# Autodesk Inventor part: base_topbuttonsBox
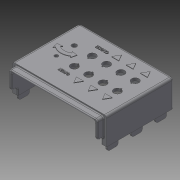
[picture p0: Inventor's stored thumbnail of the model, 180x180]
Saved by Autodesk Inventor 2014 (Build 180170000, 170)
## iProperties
Created: 2014-04
Part Number: base_topbuttonsBox
Material: Generic
Document SubType Name: Modeling
Designer: t_emanb
Density: 1 g/cm^3
Appearance: Default
Author: t_emanb
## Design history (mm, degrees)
sketch "Sketch1"
  geometry: L1 (0, 0)-(133.35, 0); L2 (133.35, 0)-(133.35, 95.25); L3 (133.35, 95.25)-(0, 95.25); L4 (0, 95.25)-(0, 0)
  constraints: 8 end point, 2 parallel, 1 horizontal, 1 perpendicular
  dimensions: "d0" = 133.35 distance of L1.start L1.end; "d1" = 95.25 distance of L3.end L1.start
extrude "Extrusion1" new body sketch "Sketch1" distance "d2" = 5.08; taper "d3" = 0 deg
sketch "Sketch2"
  geometry: L1 (0, 0)-(-133.35, 0) reference; L2 (0, 95.25)-(0, 0) reference; L3 (-133.35, 95.25)-(0, 95.25) reference; L4 (-133.35, 0)-(-133.35, 95.25) reference; L5 (-7.62, 95.25)-(-7.62, 7.62); L6 (-7.62, 7.62)-(-125.73, 7.62); L7 (-125.73, 7.62)-(-125.73, 95.25)
  constraints: 6 end point, 2 point on line
  dimensions: "d4" = 7.62 distance between parallel lines of L1 L6; "d5" = 7.62 distance between parallel lines of L2 L5 (= d4); "d6" = 7.62 distance between parallel lines of L4 L7 (= d4)
extrude "Extrusion2" join sketch "Sketch2" distance "d7" = 33.02; taper "d8" = 0 deg
sketch "Sketch3" dims "d24" = 25.4, "d104" = 25.4
  geometry: L1 (0, 0)-(-133.35, 0) reference; L2 (-133.35, 0)-(-133.35, -95.25) reference; L3 (-133.35, -95.25)-(0, -95.25) reference; L4 (-62.65, -37.9)-(-62.65, -36.829); L5 (-64.35, -36.829)-(-64.35, -37.9); L6 (-64.35, -37.9)-(-62.65, -37.9); L7 (-64.35, -51)-(-62.65, -51); L8 (-64.35, -52.071)-(-64.35, -51); L9 (-62.65, -51)-(-62.65, -52.071); L10 (-42.33, -37.9)-(-42.33, -36.829); L11 (-43.18, -26.6)-(-43.18, -33.684); L12 (-17.78, -19.05)-(-17.78, -69.85); L13 (-43.18, -19.05)-(-43.18, -69.85); L14 (-66.675, -6.762)-(-66.675, -84.867); L15 (-115.57, -19.05)-(-17.78, -19.05); L16 (-17.78, -69.85)-(-115.57, -69.85); L17 (-115.57, -44.45)-(-17.78, -44.45); L18 (-115.57, -69.85)-(-115.57, -19.05); L19 (-84.67, -36.829)-(-84.67, -37.9); L20 (-84.67, -37.9)-(-82.97, -37.9); L21 (-82.97, -37.9)-(-82.97, -36.829); L22 (-44.03, -52.071)-(-44.03, -51); L23 (-42.33, -51)-(-42.33, -52.071); L24 (-44.03, -51)-(-42.33, -51); L25 (-44.03, -36.829)-(-44.03, -37.9); L26 (-44.03, -37.9)-(-42.33, -37.9); L27 (-84.67, -52.071)-(-84.67, -51); L28 (-84.67, -51)-(-82.97, -51); L29 (-82.97, -51)-(-82.97, -52.071); L30 (-66.675, -95.25)-(-66.675, 0); L31 (-23.71, -37.9)-(-22.01, -37.9); L32 (-22.01, -37.9)-(-22.01, -36.829); L33 (-23.71, -36.829)-(-23.71, -37.9); L34 (-23.71, -51)-(-22.01, -51); L35 (-22.01, -51)-(-22.01, -52.071); L36 (-23.71, -52.071)-(-23.71, -51); C1 r 3.4 at (-109.22, -31.75); C2 r 2.54 at (-109.22, -57.15); A1 r 5.15 centre (-63.5, -31.75) between (-62.65, -36.829) and (-64.35, -36.829); A2 r 5.15 centre (-63.5, -57.15) between (-64.35, -52.071) and (-62.65, -52.071); A3 r 5.15 centre (-83.82, -31.75) between (-82.97, -36.829) and (-84.67, -36.829); A4 r 5.15 centre (-43.18, -57.15) between (-44.03, -52.071) and (-42.33, -52.071); A5 r 5.15 centre (-43.18, -31.75) between (-42.33, -36.829) and (-44.03, -36.829); A6 r 5.15 centre (-83.82, -57.15) between (-84.67, -52.071) and (-82.97, -52.071); A7 r 5.15 centre (-22.86, -31.75) between (-22.01, -36.829) and (-23.71, -36.829); A8 r 5.15 centre (-22.86, -57.15) between (-23.71, -52.071) and (-22.01, -52.071); 3 further points
  constraints: 66 end point, 20 point on circle, 10 centre point, 6 symmetric about line, 4 midpoint, 4 parallel, 4 perpendicular, 4 point on line, 3 horizontal, 1 collinear, 1 vertical alignment, 60 other
  dimensions: "d13" = 50.8 distance of L12.start L12.end; "d14" = 10.3 diameter of A5; "d15" = 1.7 distance of L25.end L10.start; "d16" = 11.3 distance from line of L11.start L26; "d18" = 25.4 distance of A4.centre A5.centre; "d19" = 20.32 distance of L25.end L5.end; "d20" = 5.08 diameter of C2; "d21" = 6.8 diameter of C1; "d22" = 25.4 distance of C2.centre C1.centre; "d23" = 6.35 distance from line of L18 C2.centre; "d25" = 17.78 distance between parallel lines of L2 L18; "d26" = 44.45 distance between parallel lines of L1 L17; "d97" = 25.4 distance of C1.centre A3.centre; "d101" = 20.32 distance of L25.end L31.start
extrude "Extrusion3" cut sketch "Sketch3" stored distance "d27" = 33.02; taper "d28" = 0 deg
sketch "Sketch4" dims "d37" = 25.4, "d48" = 25.4
  geometry: L1 (-133.35, 0)-(0, 0) reference; L2 (-7.62, 7.62)-(-125.73, 7.62) reference; L3 (-125.73, 7.62)-(-125.73, 95.25) reference; L4 (-133.35, 95.25)-(-133.35, 0) reference; L5 (-125.73, 4.953)-(-110.49, 4.953); L6 (-110.49, 4.953)-(-110.49, 2.667); L7 (-110.49, 2.667)-(-125.73, 2.667); L8 (-125.73, 2.667)-(-125.73, 4.953); L9 (-76.2, 2.667)-(-91.44, 2.667); L10 (-76.2, 4.953)-(-76.2, 2.667); L11 (-91.44, 4.953)-(-76.2, 4.953); L12 (-91.44, 2.667)-(-91.44, 4.953); L13 (-41.91, 2.667)-(-57.15, 2.667); L14 (-41.91, 4.953)-(-41.91, 2.667); L15 (-57.15, 4.953)-(-41.91, 4.953); L16 (-57.15, 2.667)-(-57.15, 4.953); L17 (-7.62, 2.667)-(-22.86, 2.667); L18 (-7.62, 4.953)-(-7.62, 2.667); L19 (-22.86, 4.953)-(-7.62, 4.953); L20 (-22.86, 2.667)-(-22.86, 4.953); L21 (-130.683, 7.62)-(-128.397, 7.62); L22 (-128.397, 7.62)-(-128.397, 22.86); L23 (-128.397, 22.86)-(-130.683, 22.86); L24 (-130.683, 22.86)-(-130.683, 7.62); L25 (-130.683, 57.15)-(-130.683, 41.91); L26 (-130.683, 41.91)-(-128.397, 41.91); L27 (-128.397, 41.91)-(-128.397, 57.15); L28 (-128.397, 57.15)-(-130.683, 57.15); L29 (-130.683, 91.44)-(-130.683, 76.2); L30 (-130.683, 76.2)-(-128.397, 76.2); L31 (-128.397, 76.2)-(-128.397, 91.44); L32 (-128.397, 91.44)-(-130.683, 91.44); L33 (-66.675, 0)-(-66.675, 95.25); L34 (-4.953, 22.86)-(-2.667, 22.86); L35 (-4.953, 7.62)-(-4.953, 22.86); L36 (-2.667, 22.86)-(-2.667, 7.62); L37 (-2.667, 7.62)-(-4.953, 7.62); L38 (-2.667, 41.91)-(-4.953, 41.91); L39 (-4.953, 41.91)-(-4.953, 57.15); L40 (-4.953, 57.15)-(-2.667, 57.15); L41 (-2.667, 57.15)-(-2.667, 41.91); L42 (-2.667, 76.2)-(-4.953, 76.2); L43 (-2.667, 91.44)-(-2.667, 76.2); L44 (-4.953, 91.44)-(-2.667, 91.44); L45 (-4.953, 76.2)-(-4.953, 91.44)
  constraints: 82 end point, 12 symmetric about line, 4 parallel, 3 horizontal, 3 perpendicular, 2 collinear, 1 midpoint, 1 vertical, 40 other
  dimensions: "d29" = 2.286 distance of L7.end L5.start; "d30" = 2.667 distance between parallel lines of L1 L7; "d31" = 15.24 distance of L6.end L7.end; "d34" = 34.29 distance of L6.end L9.start; "d40" = 2.286 distance of L21.start L21.end (= d29); "d41" = 15.24 distance of L23.end L21.start (= d31); "d42" = 2.667 distance between parallel lines of L4 L24 (= d30); "d45" = 34.29 distance of L23.end L25.start
extrude "Extrusion4" join sketch "Sketch4" distance "d50" = 8.89; taper "d51" = 0 deg
sketch "Sketch6"
  geometry: L1 (7.62, -5.08)-(125.73, -5.08) reference; L2 (125.73, -5.08)-(125.73, -38.1) reference; L3 (133.35, -38.1)-(133.35, 0) reference; L4 (7.62, -5.08)-(7.62, -38.1) reference; L5 (7.62, -27.94)-(3.81, -27.94); L6 (3.81, -27.94)-(3.81, -2.54); L7 (3.81, -2.54)-(129.54, -2.54); L8 (129.54, -2.54)-(129.54, -27.94); L9 (129.54, -27.94)-(125.73, -27.94); 1 further point
  constraints: 10 end point, 3 perpendicular, 2 parallel, 2 point on line, 1 collinear
  dimensions: "d55" = 2.54 distance between parallel lines of L7 L1; "d56" = 3.81 distance between parallel lines of L8 L2; "d57" = 3.81 distance between parallel lines of L4 L6; "d58" = 25.4 distance of L5.end L6.end
extrude "Extrusion6" join sketch "Sketch6" distance "d59" = 8.89; taper "d60" = 0 deg
sketch "Sketch7"
  geometry: L1 (-42.33, 52.071)-(-42.33, 51) reference; L2 (-42.33, 51)-(-44.03, 51) reference; L3 (-44.03, 51)-(-44.03, 52.071) reference; L4 (-44.03, 36.829)-(-44.03, 37.9) reference; L5 (-44.03, 37.9)-(-42.33, 37.9) reference; L6 (-42.33, 37.9)-(-42.33, 36.829) reference; L7 (-64.35, 36.829)-(-64.35, 37.9) reference; L8 (-64.35, 37.9)-(-62.65, 37.9) reference; L9 (-62.65, 37.9)-(-62.65, 36.829) reference; L10 (-64.35, 51)-(-64.35, 52.071) reference; L11 (-62.65, 52.071)-(-62.65, 51) reference; L12 (-62.65, 51)-(-64.35, 51) reference; L13 (-84.67, 36.829)-(-84.67, 37.9) reference; L14 (-84.67, 37.9)-(-82.97, 37.9) reference; L15 (-82.97, 37.9)-(-82.97, 36.829) reference; L16 (-82.97, 52.071)-(-82.97, 51) reference; L17 (-82.97, 51)-(-84.67, 51) reference; L18 (-84.67, 51)-(-84.67, 52.071) reference; L19 (-116.205, 67.31)-(-15.875, 67.31); L20 (-12.7, 64.135)-(-12.7, 24.765); L21 (-15.875, 21.59)-(-116.205, 21.59); L22 (-119.38, 24.765)-(-119.38, 64.135); C1 r 2.54 at (-109.22, 57.15) reference; C2 r 3.4 at (-109.22, 31.75) reference; A1 r 5.15 centre (-43.18, 57.15) between (-42.33, 52.071) and (-44.03, 52.071) reference; A2 r 5.15 centre (-43.18, 31.75) between (-44.03, 36.829) and (-42.33, 36.829) reference; A3 r 5.15 centre (-63.5, 31.75) between (-64.35, 36.829) and (-62.65, 36.829) reference; A4 r 5.15 centre (-63.5, 57.15) between (-62.65, 52.071) and (-64.35, 52.071) reference; A5 r 5.15 centre (-83.82, 31.75) between (-84.67, 36.829) and (-82.97, 36.829) reference; A6 r 5.15 centre (-83.82, 57.15) between (-82.97, 52.071) and (-84.67, 52.071) reference; A7 r 3.175 centre (-116.205, 64.135) between (-116.205, 67.31) and (-119.38, 64.135); A8 r 3.175 centre (-116.205, 24.765) between (-119.38, 24.765) and (-116.205, 21.59); A9 r 3.175 centre (-15.875, 24.765) between (-15.875, 21.59) and (-12.7, 24.765); A10 r 3.175 centre (-15.875, 64.135) between (-12.7, 64.135) and (-15.875, 67.31); A11 r 5.15 centre (-22.86, 57.15) between (-22.01, 52.071) and (-23.71, 52.071) reference; 1 further point
  constraints: 8 end point, 8 point on circle, 8 tangent, 4 centre point, 3 equal radius, 2 parallel, 1 horizontal, 1 perpendicular
  dimensions: "d61" = 10.16 distance from line of A3.centre L21; "d62" = 10.16 distance from line of A4.centre L19; "d64" = 10.16 distance from line of L22 C2.centre; "d65" = 3.175 radius of A7; "d113" = 10.16 distance from line of L20 A11.centre
extrude "Extrusion7" cut sketch "Sketch7" distance "d66" = 1.27; taper "d67" = 0 deg
sketch "Sketch8" dims "d75" = 25.4, "d111" = 25.4
  geometry: L1 (-133.35, 0)-(-133.35, -95.25) reference; L2 (-83.82, -10.644)-(-78.74, -19.443); L3 (-78.74, -19.443)-(-88.9, -19.443); L4 (-88.9, -19.443)-(-83.82, -10.644); L5 (-43.18, -31.75)-(-43.18, -57.15); L6 (-43.18, -44.45)-(-133.35, -44.45); L7 (-68.58, -19.443)-(-63.5, -10.644); L8 (-63.5, -10.644)-(-58.42, -19.443); L9 (-58.42, -19.443)-(-68.58, -19.443); L10 (-48.26, -19.443)-(-43.18, -10.644); L11 (-43.18, -10.644)-(-38.1, -19.443); L12 (-38.1, -19.443)-(-48.26, -19.443); L13 (-78.74, -69.457)-(-88.9, -69.457); L14 (-58.42, -69.457)-(-68.58, -69.457); L15 (-68.58, -69.457)-(-63.5, -78.256); L16 (-83.82, -78.256)-(-78.74, -69.457); L17 (-88.9, -69.457)-(-83.82, -78.256); L18 (-38.1, -69.457)-(-48.26, -69.457); L19 (-43.18, -78.256)-(-38.1, -69.457); L20 (-48.26, -69.457)-(-43.18, -78.256); L21 (-63.5, -78.256)-(-58.42, -69.457); L22 (0, -95.25)-(0, 0) reference; L23 (-109.22, -31.75)-(-120.256, -47.511); L24 (-109.22, -31.75)-(-98.184, -47.511); L25 (-109.22, -31.75)-(-109.22, -57.15); L26 (-115.885, -41.269)-(-123.451, -42.173); L27 (-123.451, -42.173)-(-121.713, -49.592); L28 (-121.713, -49.592)-(-120.256, -47.511); L29 (-117.342, -43.35)-(-115.885, -41.269); L30 (-102.555, -41.269)-(-94.989, -42.173); L31 (-94.989, -42.173)-(-96.727, -49.592); L32 (-96.727, -49.592)-(-98.184, -47.511); L33 (-101.098, -43.35)-(-102.555, -41.269); L34 (-17.78, -19.443)-(-27.94, -19.443); L35 (-27.94, -19.443)-(-22.86, -10.644); L36 (-22.86, -10.644)-(-17.78, -19.443); L37 (-17.78, -69.457)-(-27.94, -69.457); L38 (-27.94, -69.457)-(-22.86, -78.256); L39 (-22.86, -78.256)-(-17.78, -69.457); L40 (-75.241, -19.48)-(-87.494, -19.48); L41 (-87.494, -19.48)-(-87.494, -16.303); L42 (-87.494, -16.303)-(-75.241, -16.303); L43 (-75.241, -16.303)-(-75.241, -19.48); L44 (-76.456, -73.506)-(-86.884, -73.506); L45 (-86.884, -73.506)-(-86.884, -70.33); L46 (-86.884, -70.33)-(-76.456, -70.33); L47 (-76.456, -70.33)-(-76.456, -73.506); C1 r 2.54 at (-109.22, -57.15) reference; C2 r 3.4 at (-109.22, -31.75) reference; C3 r 10.351 at (-109.22, -31.75); A1 r 5.15 centre (-43.18, -57.15) between (-44.03, -52.071) and (-42.33, -52.071) reference; A2 r 5.15 centre (-43.18, -31.75) between (-42.33, -36.829) and (-44.03, -36.829) reference; A3 r 5.15 centre (-83.82, -31.75) between (-82.97, -36.829) and (-84.67, -36.829) reference; A4 r 14.161 centre (-109.22, -31.75) between (-117.342, -43.35) and (-101.098, -43.35); A5 r 19.241 centre (-109.22, -31.75) between (-120.256, -47.511) and (-98.184, -47.511); 8 further points
  constraints: 74 end point, 15 symmetric about line, 4 point on circle, 4 point on line, 3 centre point, 3 coincident, 2 collinear, 2 equal length, 2 horizontal, 2 perpendicular, 1 midpoint, 1 parallel, 1 vertical alignment, 40 other
  dimensions: "d68" = 10.16 distance of L2.end L3.end; "d69" = 15.24 distance of A3.centre point (-83.82, -16.51); "d72" = 20.32 distance of point (-83.82, -16.51) point (-63.5, -16.51); "d79" = 20.701 diameter of C3; "d80" = 3.81 radial gap between concentric circles of C3 A4; "d81" = 5.08 radial gap between concentric circles of A5 A4; "d82" = 70 deg angle of L24 L23; "d83" = 7.62 distance of L26.start L26.end; "d84" = 2.54 distance of L27.end L23.end; "d108" = 20.32 distance of L11.end L34.start
extrude "Extrusion8" join sketch "Sketch8" distance "d77" = 0.762; taper "d78" = 0 deg
sketch "Sketch9"
  geometry: L1 (0, -38.1)-(0, 0) reference; L2 (95.25, -38.1)-(0, -38.1) reference; L3 (22.86, -20.32)-(41.402, -20.32); L4 (41.402, -20.32)-(41.402, -33.02); L5 (41.402, -33.02)-(22.86, -33.02); L6 (22.86, -33.02)-(22.86, -20.32); C1 r 3.175 at (52.299, -26.67); 1 further point
  constraints: 8 end point, 2 parallel, 1 centre point, 1 horizontal, 1 perpendicular
  dimensions: "d85" = 18.542 distance of L4.end L5.end; "d86" = 12.7 distance of L5.end L3.start; "d87" = 5.08 distance between parallel lines of L2 L5; "d88" = 22.86 distance between parallel lines of L1 L6; "d89" = 6.35 diameter of C1
extrude "Extrusion9" cut sketch "Sketch9" stored distance "d90" = 1.27; taper "d91" = 0 deg
fillet "Fillet1" dims "d92" = 3.175
fillet "Fillet2" dims "d93" = 3.175
fillet "Fillet3" dims "d94" = 3.048
fillet "Fillet4" dims "d95" = 1.27
body "Solid1"
